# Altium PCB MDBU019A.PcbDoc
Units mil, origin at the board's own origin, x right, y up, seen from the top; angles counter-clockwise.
Board outline 2500 x 2300 mil, 2 copper layers (Top Layer, Bottom Layer), stack 62 mil thick; 49 components, 19 nets, 113 pads, 75 vias.
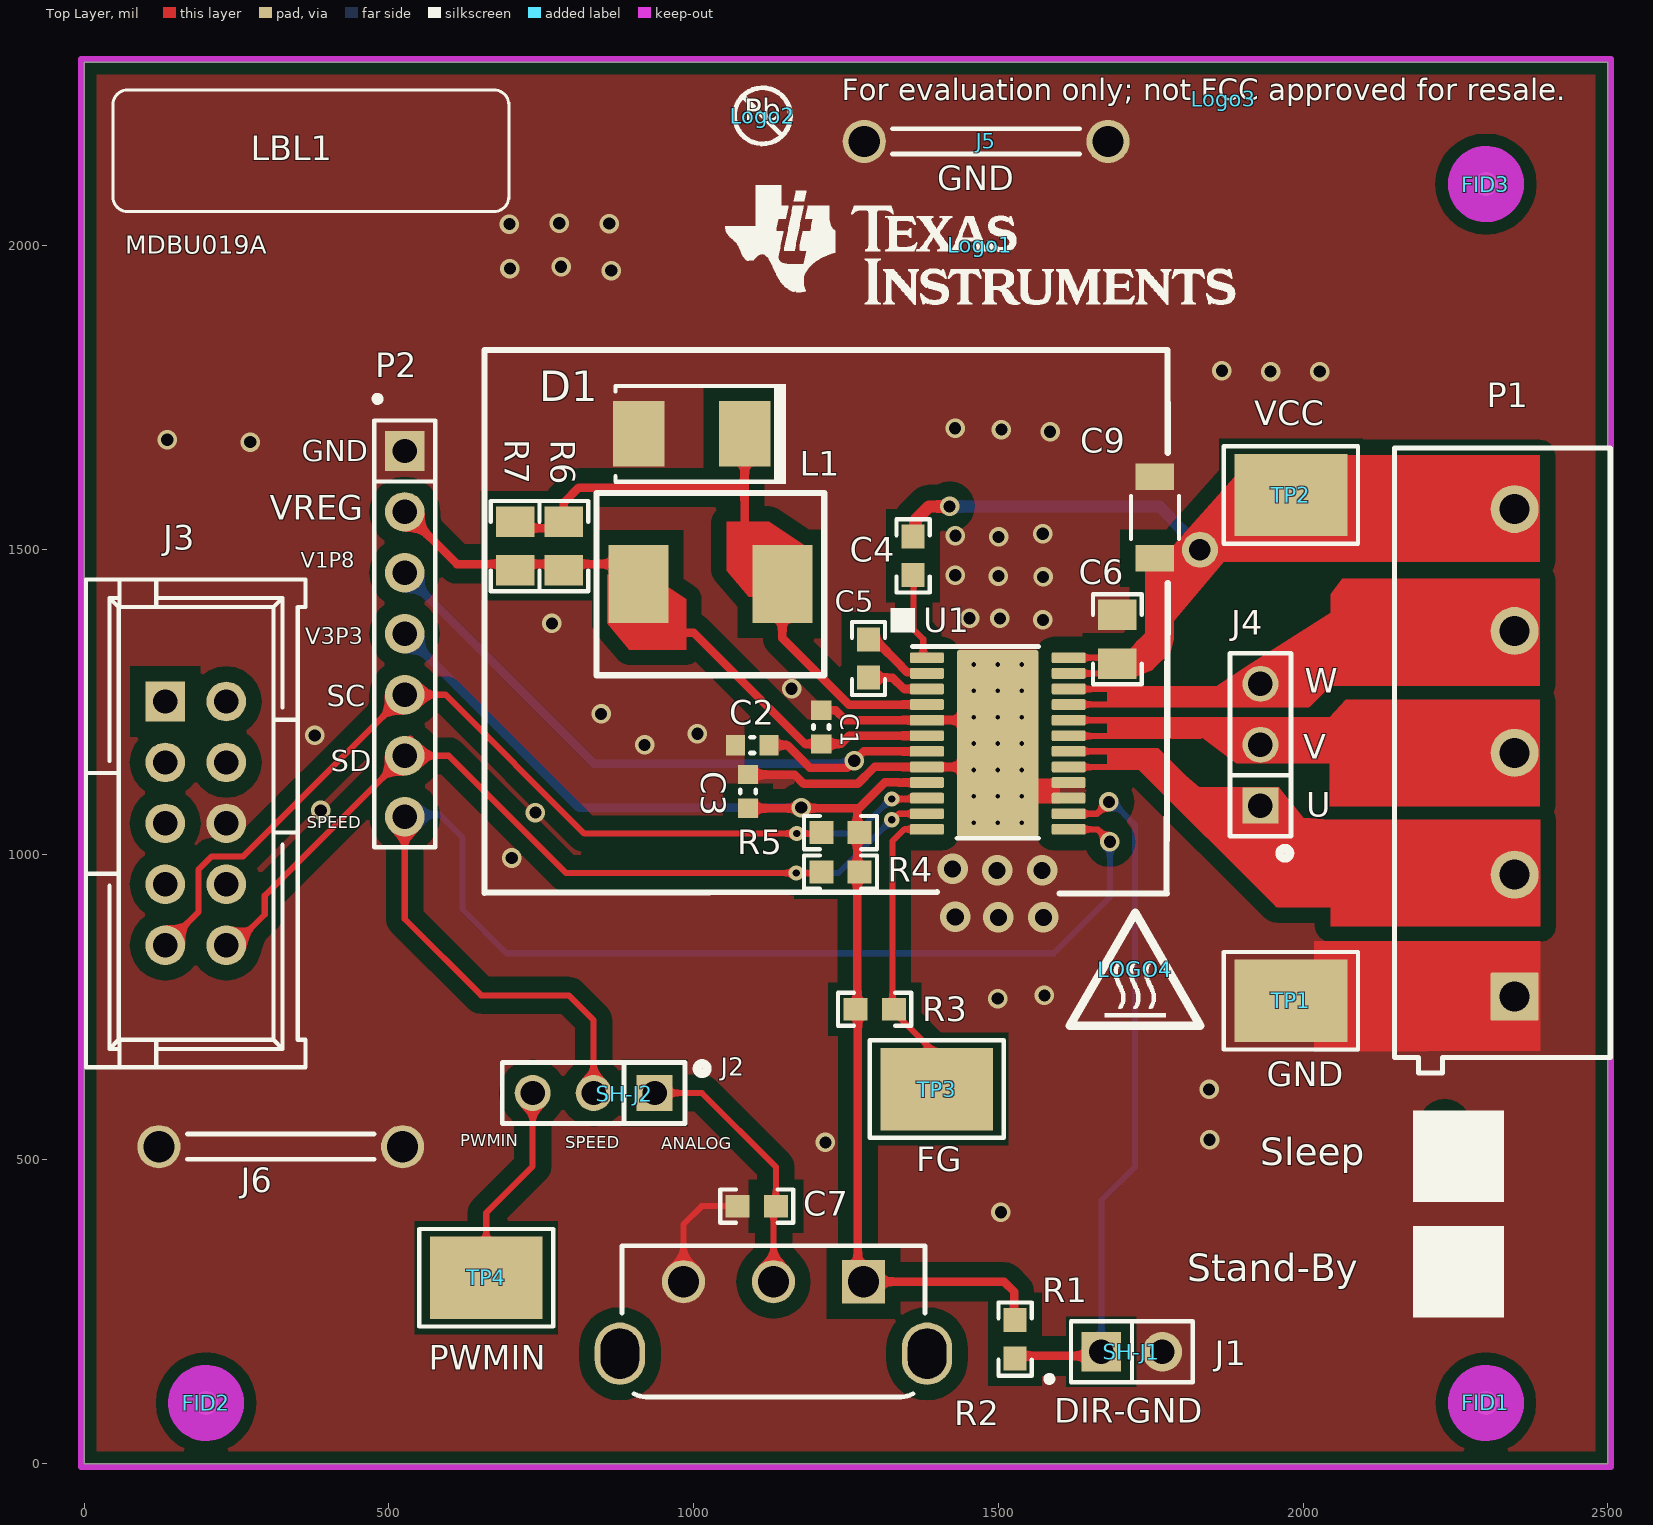
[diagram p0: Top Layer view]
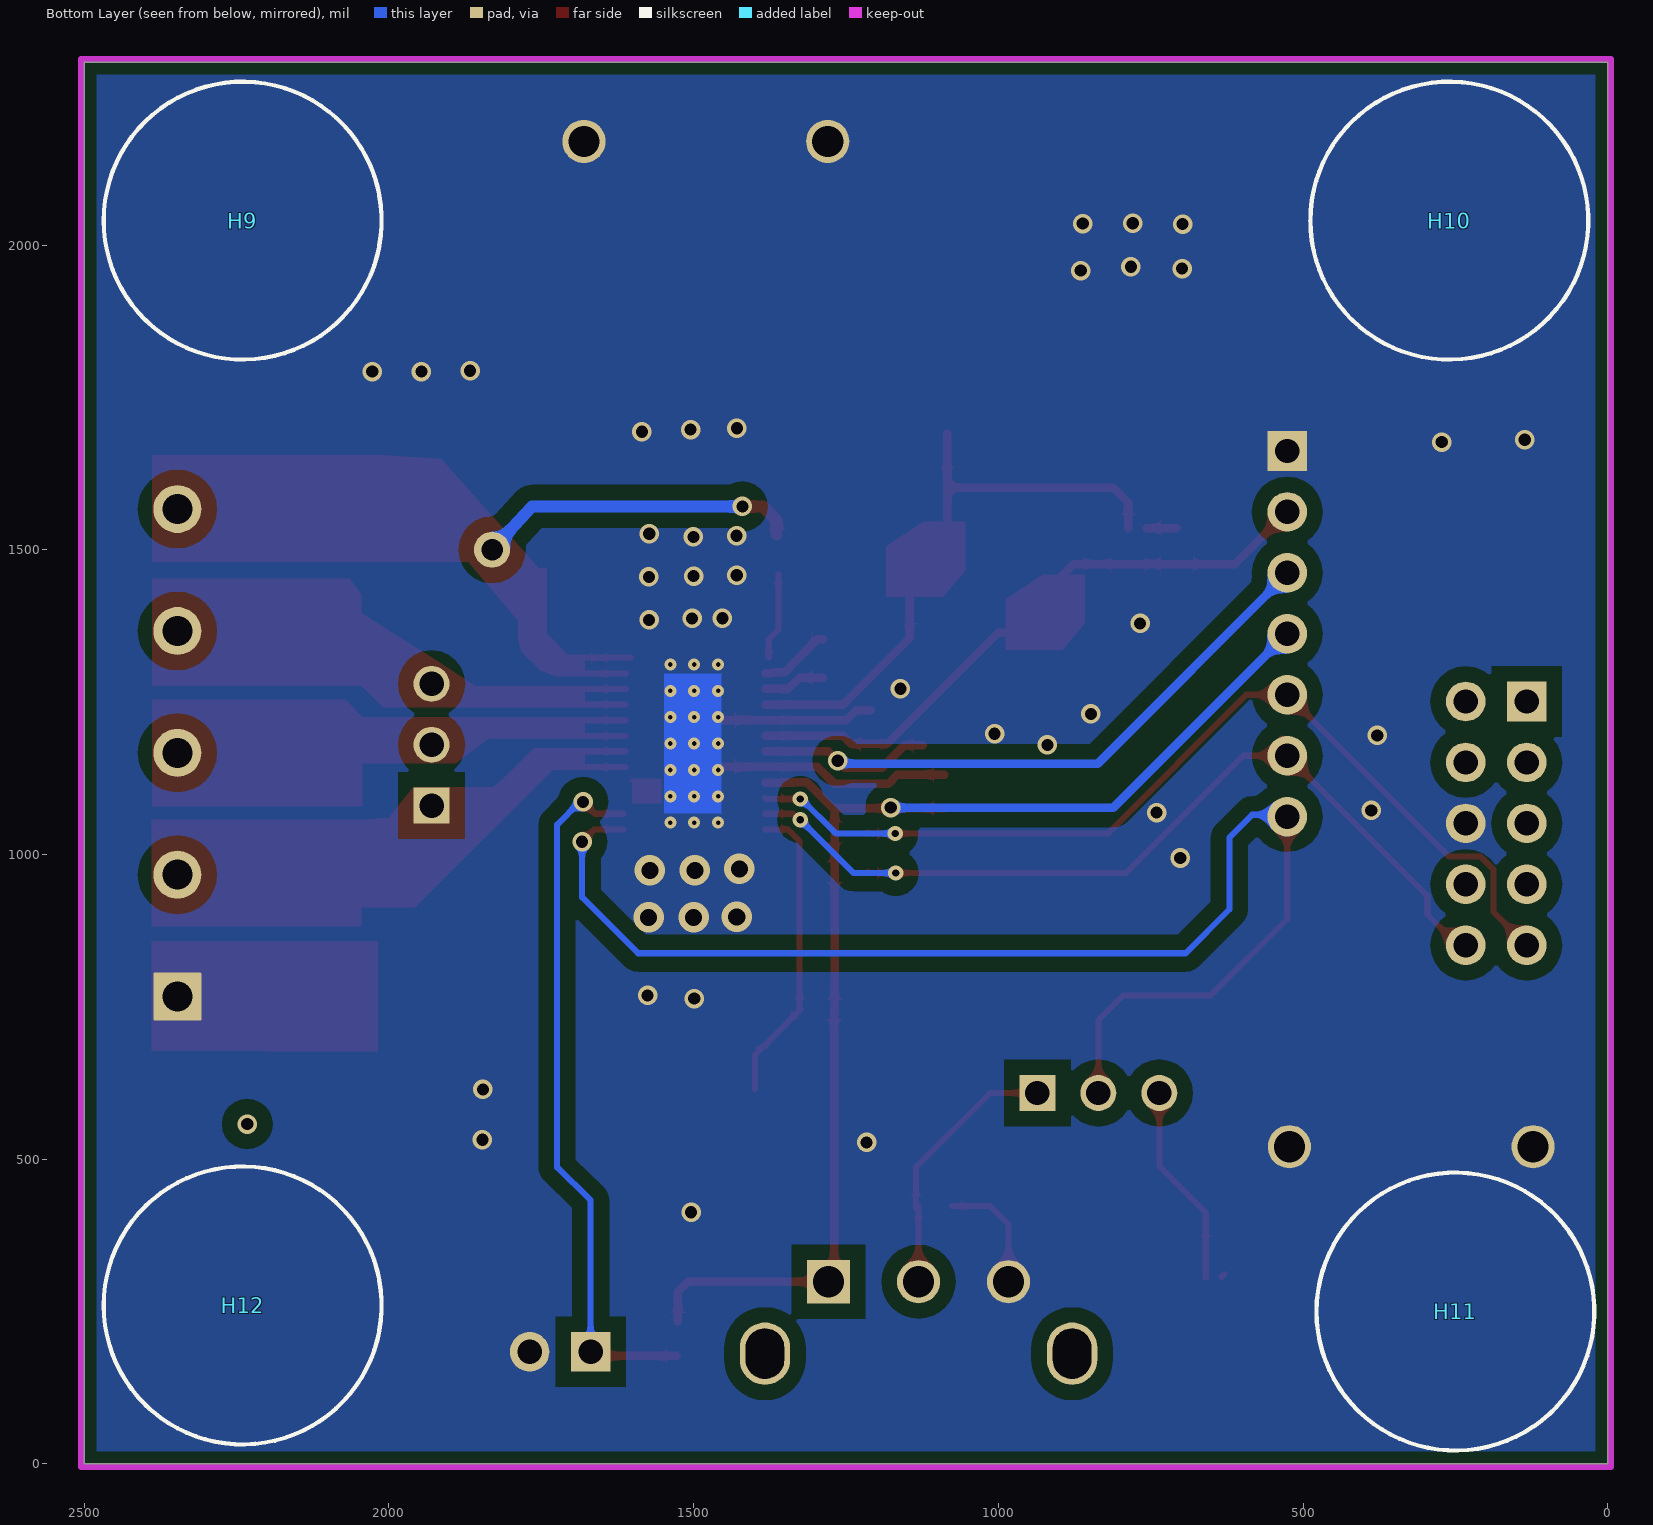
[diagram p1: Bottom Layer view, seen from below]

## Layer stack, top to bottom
Top Solder: solder mask 0.4, Solder Resist, Dk 3.5
Top Layer: signal copper 1.4
Dielectric1: core 59.2, FR-4, Dk 4.8
Bottom Layer: signal copper 1.4
Bottom Solder: solder mask 0.4, Solder Resist, Dk 3.5

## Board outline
0,0 0,2300 2500,2300 2500,0

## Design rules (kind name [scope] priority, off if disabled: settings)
AcuteAngle [All] p1: minimum=4.50000000000000E+0001 checktracksonly=FALSE
AssemblyTestPointUsage [All] p1: valid=2
Clearance Clearance_Keepouts [((IsTrack Or IsArc) And Not InPoly) And IsFree and IsKeepOut vs ((IsTrack Or IsArc) And Not InPoly) And IsFree and IsKeepOut] p1: gap=0
Clearance Clearance_BoardEdge_MountingHoles [OnCopper and InComponentClass('Mounting Holes') vs IsKeepOut] p2: gap=40
Clearance Clearance_BoardEdge_Poly [OnCopper and InPoly vs IsKeepOut] p3: gap=20
Clearance Clearance_BoardEdge [OnCopper and Not InComponentClass('Logo') and not InComponentClass('FiducialMark') and not InRegion(1000,500,4000,800) and Not IsKeepout vs IsKeepOut] p4: gap=75
Clearance Clearance_Poly [InPolygon] p5: gap=25
Clearance [All] p6: gap=7.84
ComponentClearance ComponentClearance_NetTies [InComponentClass('NetTies')] p1: gap=0 collisioncheckmode=3 verticalgap=0 showdistances=FALSE
ComponentClearance ComponentClearance_Shunt [InComponentClass('Header') vs InComponentClass('Shunt')] p2: gap=0 collisioncheckmode=3 verticalgap=0 showdistances=FALSE
ComponentClearance ComponentClearance_1 [All] p3: gap=10 collisioncheckmode=3 verticalgap=10 showdistances=FALSE
ComponentClearance ComponentClearance_Logo [InComponentClass('Logo')] p4: gap=50 collisioncheckmode=3 verticalgap=10 showdistances=FALSE
ComponentClearance ComponentClearance_ScrewToNut [(HasFootprint('NY PMS 440 0025 PH')) vs (HasFootprint('Keystone_1902C'))] p5: gap=5 collisioncheckmode=3 verticalgap=10 showdistances=FALSE
ComponentClearance ComponentClearance_MountingHoles [InComponentClass('Mounting Holes')] p6: gap=250 collisioncheckmode=3 verticalgap=100000 showdistances=FALSE
ComponentClearance ComponentClearance_SmallPassives [HasFootprint('0201*') or HasFootprint('0402*') or HasFootprint('0508') or HasFootprint('0603*') or HasFootprint('0612') or HasFootprint('0805*') or HasFootprint('0815*') or HasFootprint('0830*') or HasFootprint('1206*') or HasFootprint('1210*') or HasFootprint('1808*') or HasFootprint('1812*') or HasFootprint('1825*') or HasFootprint('2010*') or HasFootprint('2220*') or HasFootprint('2225*') or HasFootprint('2512*') or HasFootprint('2728*') or HasFootprint('3518*') vs HasFootprint('0201*') or HasFootprint('0402*') or HasFootprint('0508') or HasFootprint('0603*') or HasFootprint('0612') or HasFootprint('0805*') or HasFootprint('0815*') or HasFootprint('0830*') or HasFootprint('1206*') or HasFootprint('1210*') or HasFootprint('1808*') or HasFootprint('1812*') or HasFootprint('1825*') or HasFootprint('2010*') or HasFootprint('2220*') or HasFootprint('2225*') or HasFootprint('2512*') or HasFootprint('2728*') or HasFootprint('3518*')] p7: gap=20 collisioncheckmode=3 verticalgap=10 showdistances=FALSE
ComponentClearance ComponentClearance_THtoSMT [IsThruComponent vs IsSMTComponent] p8: gap=100 collisioncheckmode=3 verticalgap=30 showdistances=FALSE
ComponentClearance ComponentClearance_THtoTH [IsThruComponent vs IsThruComponent] p9: gap=118.11 collisioncheckmode=3 verticalgap=30 showdistances=FALSE
DiffPairsRouting [All] p1: maxlimit=100 minlimit=10 mostfreqgap=10 toplayer_minwidth=15 toplayer_maxwidth=15 toplayer_prefwidth=15 bottomlayer_minwidth=15 bottomlayer_maxwidth=15 bottomlayer_prefwidth=15 maxuncoupledlength=1000
FabricationTestPointUsage TestPointUsage [All] p1: valid=2 allowmultiple=FALSE
FabricationTestpoint Testpoint [All] p1: side=3 testpointundercomponent=TRUE minsize=40 maxsize=100 preferedsize=60 minholesize=0 maxholesize=40 preferedholesize=32 testpointgrid=1 allowsidetop=TRUE allowsidebottom=TRUE usegrid=TRUE gridtolerance=0.01
FanoutControl Fanout_LCC [IsLCC] p1: bgadir=Out bgaviamode=Centered fanoutstyle=Auto fanoutdirection=Alternating viagrid=1 // Fanout_LCC (Default Rule)
FanoutControl Fanout_BGA [IsBGA] p2: bgadir=Out bgaviamode=Centered fanoutstyle=Auto fanoutdirection=Alternating viagrid=1 // Fanout_BGA (Default Rule)
FanoutControl Fanout_Default [All] p4: bgadir=Out bgaviamode=Centered fanoutstyle=Auto fanoutdirection=Alternating viagrid=1 // Fanout_Default (Default Rule)
FanoutControl Fanout_Small [(CompPinCount < 5)] p5: bgadir=Out bgaviamode=Centered fanoutstyle=Auto fanoutdirection=OutThenIn viagrid=1 // Fanout_Small (Default Rule)
HoleSize [All] p1: absolutevalues=TRUE maxlimit=251 minlimit=7 maxpercent=80.000 minpercent=20.000
MinimumAnnularRing MinimumAnnularRing_ThermalPadVias [IsVia and InAnyComponent] p1: minimumring=5.91
MinimumAnnularRing [All] p2: minimumring=6
MinimumSolderMaskSliver MinimumSolderMaskSliver_Logo [InComponentClass('Logo') vs InComponentClass('Logo')] p1: minsoldermaskwidth=0.7
MinimumSolderMaskSliver [All] p2: minsoldermaskwidth=3.94
PlaneConnect [All] p1: planeconnectstyle=Relief reliefexpansion=10 reliefentries=4 reliefconductorwidth=10 reliefairgap=10
PolygonConnect PolygonConnect_5 [All vs IsNamedPolygon('Bottom Layer-GND')] p1: connectstyle=Direct reliefconductorwidth=10 reliefentries=4 polygonreliefangle="90 Angle" airgapwidth=10
PolygonConnect PolygonConnect_4 [All vs IsNamedPolygon('Top Layer-GND')] p2: connectstyle=Direct reliefconductorwidth=10 reliefentries=4 polygonreliefangle="90 Angle" airgapwidth=10
PolygonConnect PolygonConnect_3 [All vs IsNamedPolygon('Top Layer-GND')] p3: connectstyle=Direct reliefconductorwidth=10 reliefentries=4 polygonreliefangle="90 Angle" airgapwidth=10
PolygonConnect PolygonConnect_2 [All vs IsNamedPolygon('Bottom Layer-GND2')] p4: connectstyle=Direct reliefconductorwidth=10 reliefentries=4 polygonreliefangle="90 Angle" airgapwidth=10
PolygonConnect PolygonConnect_1 [All vs IsNamedPolygon('Top Layer-GND2')] p5: connectstyle=Direct reliefconductorwidth=10 reliefentries=4 polygonreliefangle="90 Angle" airgapwidth=10
PolygonConnect [All] p6: connectstyle=Relief reliefconductorwidth=10 reliefentries=4 polygonreliefangle="90 Angle" airgapwidth=10
RoutingVias [All] p1: holewidth=16 width=34 viastyle="Through Hole" minholewidth=7.87 minwidth=19 maxholewidth=40 maxwidth=65
RoutingVias ThermalPadVias [IsVia and InAnyComponent] p2: holewidth=7.87 width=19.68 viastyle="Through Hole" minholewidth=7.87 minwidth=19.68 maxholewidth=12.99 maxwidth=23.62
SMDToCorner [All] p1: distance=30000
SilkToSilkClearance SilkToSilkClearance_pblogo [(HasFootprint('Pb-Free_Overlay_Medium') OR HasFootprint('Pb-Free_Overlay_Small')) vs (HasFootprint('Pb-Free_Overlay_Medium') OR HasFootprint('Pb-Free_Overlay_Small'))] p1: silktosilkclearance=0
SilkToSilkClearance [All] p2: silktosilkclearance=5
SilkToSolderMaskClearance SilkscreenOverComponentPads [IsPad] p1: minsilkscreentomaskgap=5 clearancetoexposedcopper=TRUE
SolderMaskExpansion [All] p1: expansion=1.97
Width [All] p1: maxlimit=100 minlimit=6 preferedwidth=10 checkconnectedcopper=TRUE
16 further rules are at their usual default settings.

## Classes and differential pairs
component class AssemblyNote: ZZ1 ZZ2 ZZ3 ZZ4 ZZ5
component class FiducialMark: FID1 FID2 FID3
component class MDBU019A_EVM_Hardware: FID1 FID2 FID3 H9 H10 H11 H12 LBL1 Logo1 Logo2 Logo3 LOGO4 SH-J1 SH-J2 ZZ1 ZZ2 ZZ3 ZZ4 ZZ5
component class Logo: Logo1
component class MDBU019A: C1 C2 C3 C4 C5 C6 C7 C9 D1 J1 J2 J3 J4 J5 J6 L1 P1 P2 R1 R2 R3 R4 R5 R6 R7 TP1 TP2 TP3 TP4 U1
component class Shunt: SH-J1 SH-J2
component class Header: J1 J2 J4 P2
component class Label: LBL1

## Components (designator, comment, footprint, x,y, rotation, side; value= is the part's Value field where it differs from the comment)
C1 "C1608X5R1A106M080AC" 0603L 1209.51,1209.03 r90 top
C2 "C1608X5R1E105K080AC" 0603L 1096.24,1179.45 r0 top
C3 "C1608X5R1E105K080AC" 0603L 1089.2,1103.43 r270 top
C4 "06035C104KAT2A" 0603 1360,1490 r270 top
C5 "06031C103KAT2A" 0603 1286.98,1321.53 r90 top
C6 "C2012X5R1H475K125AB" 0805_HV 1695.32,1353.14 r270 top
C7 "06035C104KAT2A" 0603 1103.64,422.9 r180 top
C9 "C3216X5R1H106K160AB" 1206_180 1756.76,1553 r90 top
D1 "VS-10BQ030HM3/5BT" SMB 996.79,1690.24 r180 top
FID1 "Fiducial" Fiducial10-30 2300,100 r90 top
FID2 "Fiducial" Fiducial10-30 200,100 r90 top
FID3 "Fiducial" Fiducial10-30 2300,2100 r90 top
H9 "SJ-5303 (CLEAR)" Bumpon_SJ5003Transparent 2240,2040 r180 bottom
H10 "SJ-5303 (CLEAR)" Bumpon_SJ5003Transparent 260,2040 r180 bottom
H11 "SJ-5303 (CLEAR)" Bumpon_SJ5003Transparent 250,250 r180 bottom
H12 "SJ-5303 (CLEAR)" Bumpon_SJ5003Transparent 2240,260 r180 bottom
J1 "90120-0122" CONN_90120-0122 1719.13,183.93 r0 top
J2 "PEC03SAAN" CONN_PEC03SAAN 835.93,608.59 r180 top
J3 "5103308-1" CONN_5103308-1 183.08,1051 r270 top
J4 "PEC03SAAN" CONN_PEC03SAAN 1930,1180 r90 top
J5 "D3082-05" Harwin_D3082-05 1480,2170 r180 top
J6 "D3082-05" Harwin_D3082-05 322.53,520.54 r180 top
L1 "DR74-470-R" DR74 1027.3,1443.61 r0 top
LBL1 "Size: 0.65\" x 0.20 \"" Label_650x200 371.95,2154.71 r0 top
Logo1 "Texas Instruments" TI_Stacked_Overlay_Small 1470,2000 r0 top
Logo2 "Pb-Free Symbol" Pb-Free_Overlay_Small 1113,2212 r0 top
Logo3 "FCC disclaimer" FCC_disclaimer 1870,2240 r0 top
LOGO4 "CAUTION HOT SURFACE" IEC_HotSurface_Small 1724.48,811.69 r0 top
P1 "ED120/5DS" On-Shore_ED120_5DS 2347.03,1166.77 r90 top
P2 "TSW-107-07-G-S" TSW-107-07-G-S 525.93,1362.05 r270 top
R1 "CRCW060310K0JNEA" 0603 1527.41,204.86 r270 top
R2 "296XD253B1N" CTS_296X 1131,299 r180 top
R3 "CRCW06034K75FKEA" 0603 1297,746 r0 top
R4 "CRCW06034K75FKEA" 0603 1241,971 r180 top
R5 "CRCW06034K75FKEA" 0603 1241,1036 r180 top
R6 "CRCW080578R7FKEA" 0805_HV 787.14,1506.04 r90 top
R7 "CRCW080578R7FKEA" 0805_HV 707.14,1506.04 r90 top
SH-J1 "969102-0000-DA" SNT-100-BK-G 1719.13,183.93 r0 top
SH-J2 "969102-0000-DA" SNT-100-BK-G 886.91,607.14 r0 top
TP1 "5016" Testpoint_Keystone_Compact 1980,760 r180 top
TP2 "5016" Testpoint_Keystone_Compact 1980,1590 r180 top
TP3 "5016" Testpoint_Keystone_Compact 1399,615 r180 top
TP4 "5016" Testpoint_Keystone_Compact 659.68,305.63 r180 top
U1 "DRV10983SQPWPRQ1" PWP0024B_N 1499,1182 r0 top
ZZ1 "This Assembly Note is for PCB labels only" AssemblyNoteLabel 188.21,3922.4 r0 top
ZZ2 "This Assembly Note will show in the PcbDoc and associated outputs" AssemblyNote 185,3829.11 r0 top
ZZ3 "This Assembly Note will show in the PcbDoc and associated outputs" AssemblyNote 185,3740.56 r0 top
ZZ4 "This Assembly Note will show in the PcbDoc and associated outputs" AssemblyNote 185,3652 r0 top
ZZ5 "With a marker put an \"x\" in the box Stand-By on the PCB" AssemblyNote 186.19,3563.52 r0 top

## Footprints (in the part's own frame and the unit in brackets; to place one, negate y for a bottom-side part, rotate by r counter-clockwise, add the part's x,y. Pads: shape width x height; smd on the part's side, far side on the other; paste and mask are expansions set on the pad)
0603 [mm] "0603 from SM-752 data"
  rect 1x0.95 smd: 1(-0.8,0) 2(0.8,0)
  silkscreen extent -1.52,-0.69 1.52,0.69, body extent -0.87,-0.47 0.87,0.47, height 1
0603L [mm] "0603 from SM-752 data"
  rect 0.8x0.85 smd: 1(-0.7,0) 2(0.7,0)
  silkscreen extent -0.07,-0.33 0.07,0.33, body extent -0.87,-0.47 0.87,0.47, height 1
0805_HV [mil] "0805 with 30mil clearance between pads"
  rect 50x63 smd: 1(-40,0) 2(40,0)
  silkscreen extent -74,-40 74,40, body extent -43,-29 43,29, height 57
1206_180 [mm] "1206_180"
  rect 1.1x1.6 smd: 1(-1.7,0) 2(1.7,0)
  silkscreen extent -0.9,-1 0.9,1, body extent -1.75,-0.95 1.75,0.95, height 1.8
AssemblyNote [mil] "Assembly Note"
AssemblyNoteLabel [mil] "Assembly Note for PCB Labels"
Bumpon_SJ5003Transparent [mil] "3M Hemispherical Bumpon transparent"
  round 1 on Mech4: 0(0,0)
  silkscreen extent -228,-228 228,228, body extent -219,-218 219,218, height 197
CONN_90120-0122 [mm] "Molex"
  rect 1.65x1.65 hole 1.016 mask+0: 1(-1.27,0)
  round 1.65 hole 1.016 mask+0: 2(1.27,0)
  silkscreen extent -3.56,-1.27 2.54,1.27, body extent -2.54,-1.27 2.54,1.27, height 9.29
CONN_5103308-1 [mm] "TE Connectivity (AMP) Rev E datasheet"
  rect 1.65x1.65 hole 1.016 mask+0: 1(-5.08,-1.27)
  round 1.65 hole 1.016 mask+0: 2(-5.08,1.27) 3(-2.54,-1.27) 4(-2.54,1.27) 5(0,-1.27) 6(0,1.27) 7(2.54,-1.27) 8(2.54,1.27) 9(5.08,-1.27) 10(5.08,1.27)
  silkscreen extent -10.16,-4.57 10.16,4.57, body extent -10.16,-4.57 10.16,4.57, height 9.87
CONN_PEC03SAAN [mm] "SULLINS"
  rect 1.5x1.5 hole 1.016: 1(-2.54,0)
  round 1.5 hole 1.016: 2(0,0) 3(2.54,0)
  silkscreen extent -4.72,-1.27 3.81,1.27, body extent -3.84,-1.3 3.84,1.3, height 8.38
CTS_296X [mm] "TH, 3-Leads, Body 6.3x12.5mm, Pitch 3.75mm"
  rect 1.8x1.8 hole 1.3: 1(-3.75,0)
  round 1.8 hole 1.3: 2(0,0) 3(3.75,0)
  oval 2.1x2.6 hole 1.6 slot 2.1 at 90 deg: MH1(-6.4,3) MH2(6.4,3)
  silkscreen extent -6.32,-1.5 6.32,4.8, body extent -7.1,-1.5 7.1,18.5, height 16.53
DR74 [mm]
  rect 2.5x3.25 smd: 1(-3,0) 2(3,0)
  silkscreen extent -4.75,-3.8 4.75,3.8, body extent -3.8,-3.8 3.8,3.8, height 4.35
FCC_disclaimer [mil]
Fiducial10-30 [mm]
  round 1 smd mask+1: 1(0,0)
  Top Layer keep-out circle w1.678: c0,0 r0.75
Harwin_D3082-05 [mm] "Shorting Plug, 10.16mm spacing, TH"
  round 1.8 hole 1.3: 1(-5.08,0) 2(5.08,0)
  silkscreen extent -3.9,-0.53 3.9,0.53, body extent -5.6,-0.52 5.61,0.52, height 6.63
IEC_HotSurface_Small [mil]
  silkscreen extent -107,-93 107,92
Label_650x200 [mil] "Thermal Transfer Label"
  round 1 on Mech13: 0(0,0)
  silkscreen extent -325,-100 325,100, body extent -325,-100 325,100, height 1
On-Shore_ED120_5DS [mm] "TH, 5-Leads, Body 25.4x9mm, Pitch 5.08mm"
  rrect5% 2x2 hole 1.25: 1(-10.16,0)
  round 2 hole 1.25: 2(-5.08,0) 3(0,0) 4(5.08,0) 5(10.16,0)
  silkscreen extent -13.34,-4 12.7,5, body extent -13.4,-4 12.7,5, height 13
Pb-Free_Overlay_Small [mil]
  silkscreen extent -46,-46 46,46
PWP0024B_N [mm] "TSOP, 24-Leads, Body 7.9x4.5mm (max), Pitch 0.65mm, IPC Medium Density"
  rrect22% 1.4x0.45 smd: 1(-2.95,3.575) 2(-2.95,2.925) 3(-2.95,2.275) 4(-2.95,1.625) 5(-2.95,0.975) 6(-2.95,0.325) 7(-2.95,-0.325) 8(-2.95,-0.975) 9(-2.95,-1.625) 10(-2.95,-2.275) 11(-2.95,-2.925) 12(-2.95,-3.575) 13(2.95,-3.575) 14(2.95,-2.925) 15(2.95,-2.275) 16(2.95,-1.625) 17(2.95,-0.975) 18(2.95,-0.325) 19(2.95,0.325) 20(2.95,0.975) 21(2.95,1.625) 22(2.95,2.275) 23(2.95,2.925) 24(2.95,3.575)
  rrect6% 3.4x7.8 smd paste-2 mask-2: 25(0,0)
  rrect4% 2.4x5.16 on Top Paste: 25(0,0)
  rrect4% 2.4x5.16 on Top Solder: 25(0,0)
  silkscreen extent -3.55,-3.95 1.7,4.05, body extent -3.21,-3.9 3.21,3.9, height 1.2
SMB [mil] "Molded Diode, 2-Leads, Body 5.4x3.6mm, IPC Medium Density, based on OnSemi component dimensions"
  rect 85x107.99 smd: 1(-87.01,0) 2(87.01,0)
  silkscreen extent -155,-82 125,82, body extent -106,-71 106,71, height 91
SNT-100-BK-G [mil] "Samtec STEP model"
  round 1 on Mech3: 0(0,0)
  body extent -100,-50 100,50, height 344
Testpoint_Keystone_Compact [mil] "Compact SMT test point"
  rect 185x135 smd: 1(0,0)
  silkscreen extent -110,-80 110,80, body extent -75,-56 75,56, height 91
TI_Stacked_Overlay_Small [mil]
  silkscreen extent -418,-98 418,98
TSW-107-07-G-S [mm] "Samtec 100mil, 1x7, 230 mil above insulator"
  rect 1.65x1.65 hole 1.016 mask+0: 1(-7.62,0)
  round 1.65 hole 1.016 mask+0: 2(-5.08,0) 3(-2.54,0) 4(0,0) 5(2.54,0) 6(5.08,0) 7(7.62,0)
  silkscreen extent -9.91,-1.27 8.89,1.27, body extent -8.89,-1.27 8.89,1.27, height 8.38

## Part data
C1: "CAP, CERM, 10 µF, 10 V, +/- 20%, X5R, 0603"
C2 C3: "CAP, CERM, 1 µF, 25 V, +/- 10%, X5R, 0603"
C4 C7: "CAP, CERM, 0.1 µF, 50 V, +/- 10%, X7R, 0603"
C5: "CAP, CERM, 0.01 µF, 100 V, +/- 10%, X7R, 0603"
C6: "CAP, CERM, 4.7 µF, 50 V, +/- 10%, X5R, 0805"
C9: "CAP, CERM, 10 µF, 50 V, +/- 10%, X5R, 1206"
D1: "Diode, Schottky, 30 V, 1 A, AEC-Q101, SMB"
FID1 FID2 FID3: "Fiducial mark.  There is nothing to buy or mount."
H9 H10 H11 H12: "Bumpon, Hemisphere, 0.44 X 0.20, Clear"
J1: "Header, 100mil, 2x1, Tin, TH"
J2 J4: "Header, 100mil, 3x1, Tin, TH"
J3: "Header (shrouded), 100mil, 5x2, Gold, TH"
J5 J6: "1mm Uninsulated Shorting Plug, 10.16mm spacing, TH"
L1: "Inductor, Shielded Drum Core, Ferrite, 47 µH, 1.15 A, 0.216 ohm, SMD"
LBL1: library part THT-14-423-10, "Thermal Transfer Printable Labels, 0.650\" W x 0.200\" H - 10,000 per roll"
Logo1: library part TI_Logo, "Texas Instrument Corporate Signature"
Logo2: library part Pb-Free
Logo3: library part FCC_disclaimer, "FCC_disclaimer"
LOGO4: library part IEC_HotSurface, "IEC 61010-1 Hot Surface Warning"
P1: "Terminal Block, 5.08 mm, 5x1, Brass, TH"
P2: "Header, 100mil, 7x1, Gold, TH"
R1: "RES, 10 k, 5%, 0.1 W, 0603"
R2: "Trimmer, 25k ohm, 0.15W, TH"
R3 R4 R5: "RES, 4.75 k, 1%, 0.1 W, 0603"
R6 R7: "RES, 78.7, 1%, 0.125 W, 0805"
SH-J1 SH-J2: "Shunt, 100mil, Gold plated, Black"
TP1 TP2 TP3 TP4: "Test Point, Compact, SMT"
U1: "Industrial, Three-Phase, Sensorless BLDC Motor Driver, PWP0024B (TSSOP-24)"
ZZ1: library part AssemblyNoteLabel
ZZ2 ZZ3 ZZ4: library part AssemblyNote
ZZ5: library part AssemblyNote, "This Assembly Note will show in the PcbDoc and associated outputs"

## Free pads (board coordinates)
  round 59.06 hole 35.43: 0(1830.74,1500)

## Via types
v1: diameter 32, hole 20, Top Layer to Bottom Layer, 44 vias
v2: diameter 19.68, hole 7.87, Top Layer to Bottom Layer, 15 vias
v3: diameter 19.68, hole 7.87, Top Layer to Bottom Layer, tented both sides, 6 vias
v4: diameter 50, hole 28, Top Layer to Bottom Layer, 6 vias
v5: diameter 25, hole 12, Top Layer to Bottom Layer, 4 vias

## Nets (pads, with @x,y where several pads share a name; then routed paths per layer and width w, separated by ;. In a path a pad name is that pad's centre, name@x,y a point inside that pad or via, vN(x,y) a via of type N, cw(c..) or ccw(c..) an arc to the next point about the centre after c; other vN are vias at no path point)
CPN: C5.1 U1.3 | length 103.5
  Top Layer w14: C5.1 1326.47,1290.03 1344.94,1271.57 U1.3
CPP: C5.2 U1.2 | length 119.4
  Top Layer w14: C5.2 1297.03,1353.02 1340.46,1309.6 1340.46,1308.88 1350.29,1299.05 1369.11,1299.05 1371,1297.16 U1.2
DIR: J1.1 R1.2 U1.14 | length 1173.8
  Top Layer w10: U1.14 1662.04,1066.84 v1(1681.36,1086.17) ; J1.1@1662.5,177.3 J1.1
  Top Layer w14: R1.2@1527.41,177.3 J1.1@1662.5,177.3
  Bottom Layer w10: J1.1 1669.13,432.63 1670.65,434.15 1724.1,486.68 1724.1,1049.08 1687.02,1086.17 v1(1681.36,1086.17) 1681.36,1078.95 v1@1680.23,1077.81
FG: R3.2 TP3.1 U1.12 | length 503.2
  Top Layer w10: U1.12 1345.28,1041.25 1326.03,1022 1326.03,747.47 1324.56,746 1399,671.56 TP3.1
GND: C1.2 C2.1 C3.1 C6.1 C7.2 C9.2 D1.2 J1.2 J3.6 J5.1 J5.2 J6.1 J6.2 P1.1 P2.1 R2.3 TP1.1 U1.5 U1.8 U1.15 U1.16 U1.25@1499,1182 | length 980.1
  Top Layer w10: R2.3 983.36,392.96 1013.3,422.9 C7.2@1076.08,422.9 ; U1.25@1510,1100 U1.25@1517.7,1092.3 ; U1.25@1510,1110 U1.25@1517.3,1117.3
  Top Layer w14: C3.1 1165.53,1130.99 1180.49,1116.03 1269.36,1116.03 1295.06,1141.72 ; C1.2 1232.99,1236.59 1249.19,1220.39 U1.5 1460.61,1220.39 v2(1499,1182) 1460.61,1143.61 U1.8 1296.95,1143.61
  Bottom Layer w20: 1481,1095 1486,1090
  other v1: 1504.07,413.03 1216.28,527.43 1846.5,531.89 1845.64,614.54 1499.09,763.65 1575.68,768.64 701.43,994.21 740.3,1068.69 388.16,1072.18 919.43,1179.83 378.28,1195.22 1006.12,1198.24 848.06,1230.54 1160.66,1272.04 767.5,1379.19 1573.05,1384.73 1502.55,1387.35 1452.74,1387.6 1573.3,1455.52 1499.97,1456.81 1429.22,1458.1 1500.23,1520.99 1429.6,1522.97 1572.72,1526.09 272.52,1676.56 136.41,1680.59 1584.85,1693.59 1504.9,1697.24 1429.07,1699.42 1946.61,1792.44 2027.41,1792.44 1866.86,1793.76 864.78,1957.97 698.64,1961.44 782.45,1964.42 697.65,2034.35 861.51,2035.16 779.48,2035.84
  other v2: 1459.63,1095.39 1499,1095.39 1538.37,1095.39 1459.63,1138.69 1499,1138.69 1538.37,1138.69 1459.63,1182 1538.37,1182 1459.63,1225.31 1499,1225.31 1538.37,1225.31 1459.63,1268.61 1499,1268.61 1538.37,1268.61
  other v3: 1459.63,1052.08 1499,1052.08 1538.37,1052.08 1459.63,1311.92 1499,1311.92 1538.37,1311.92
  other v4: 1500.01,896.65 1574.03,896.65 1429.3,897.76 1497.8,973.99 1571.82,973.99 1424.88,976.2
NetC7_1: C7.1 J2.1 R2.2 | length 483.1
  Top Layer w10: J2.1 1013.57,608.59 1134.84,487.32 C7.1@1134.84,419.25 ; R2.2@1118.39,286.39 1113.16,286.39 1113.16,306.39 1123.61,316.84 R2.2@1125.52,316.84 ; R2.2 1131.2,299.2 C7.1@1131.2,422.9
PWMIN: J2.3 TP4.1 | length 340.5
  Top Layer w10: TP4.1@629.24,311.31 TP4.1@633.47,307.09 ; TP4.1 659.68,411.96 735.93,488.2 J2.3
SCL: J3.9 P2.5 R5.2 U1.10 | length 1621.2
  Top Layer w10: J3.9 187.76,905.68 187.76,975.54 209.03,996.82 260.7,996.82 P2.5 593.12,1262.05 820.87,1034.3 v5(1169.36,1034.3) 1211.74,1034.3 R5.2@1213.44,1036 ; v5(1325,1091) 1381.43,1091 U1.10
  Bottom Layer w10: v5(1169.36,1034.3) 1266.46,1034.3 ; 1268.59,1036.43 1323.16,1091 v5(1325,1091)
SDA: J3.10 P2.6 R4.2 U1.11 | length 1463.5
  Top Layer w10: J3.10 245.75,851 296.24,901.48 296.24,932.36 P2.6 598.2,1162.05 790.73,969.52 v5(1168.49,969.52) 1211.96,969.52 R4.2@1213.44,971 ; P2.6@535,1188.82 P2.6@535,1190 ; v5(1325,1057) 1326.84,1057 1336.68,1066.84 U1.11
  Bottom Layer w10: v5(1168.49,969.52) 1237.52,969.52 v5(1325,1057)
SPEED: J2.2 P2.7 U1.13 | length 2285.8
  Top Layer w10: P2.7 525.93,894.1 651.22,768.81 795.14,768.81 835.93,728.03 J2.2 ; U1.13 1658.11,1041.25 1658.59,1040.77 1663.23,1040.77 v1(1683,1021)
  Bottom Layer w10: P2.7 P2.7@525.93,1038.5 ; P2.7@530.03,1034.4 P2.7@525.93,1038.5 ; v1(1683,1021) 1683,929.63 1591.22,837.86 692.77,837.86 620.95,909.69 620.95,1027.71 583.51,1065.15 499.28,1065.15 P2.7@525.93,1038.5
SW: D1.1 L1.2 R6.2 R7.2 U1.4 | length 955.9
  Top Layer w14: R7.2@707.14,1535.56 R6.2@756.58,1535.56 ; R6.2@787.14,1535.56 787.14,1577.72 811.18,1601.76 1083.8,1601.76 ; 1083.8,1488.63 1083.8,1601.76 ; D1.1 1083.8,1601.76 ; L1.2@1145.55,1428.46 1145.41,1355.05 1254.49,1245.98 U1.4
U: J4.1 P1.2 U1.17 U1.18 | length 1202.6
  Top Layer w10: U1.17@1611.7,1143.3 1732.7,1143.3 1958,918 2083,918 ; U1.18@1611.7,1169.3 1760.7,1169.3 1911,1019 2084,1019 ; 2083,916 2084,917 2084,919
  Top Layer w40: 2084,919 2084,967 2084,1019
V: J4.2 P1.3 U1.19 U1.20 | length 781.8
  Top Layer w10: U1.19@1611.7,1194.3 1830.7,1194.3 ; U1.20@1611.7,1220.3 2074.3,1220.3 2075,1221 ; 2084,1124 2086,1122
  Top Layer w40: 2084,1124 2084,1162 2084,1219 ; 2290,1162 2291,1161
V1P8: C2.2 P2.3 U1.7 | length 1155.6
  Top Layer w14: C2.2@1124.3,1179.45 1153.61,1179.45 1190.82,1142.24 1251.96,1142.24 v1(1263.52,1153.8) 1278.92,1169.2 U1.7
  Bottom Layer w14: P2.3 525.93,1460.04 836.98,1148.99 1258.71,1148.99 v1(1263.52,1153.8)
V3P3: C3.2 P2.4 R1.1 R2.1 R3.1 R4.1 R5.1 U1.9 | length 2151.4
  Top Layer w10: R3.1@1268.56,746.88 R3.1@1269.44,746 ; R1.1@1525.73,234.09 R1.1@1527.41,232.42
  Top Layer w14: C3.2@1089.22,1075.85 1271.18,1075.85 1313.68,1118.34 1336.32,1118.34 1336.64,1118.02 U1.9 ; R3.1@1268.56,746.88 1268.56,971 1268.56,1036 1268.56,1073.22 ; R2.1@1269.44,308.2 R3.1@1269.44,746 ; R2.1 1509.45,299 1525.73,282.72 R1.1@1525.73,234.09
  Bottom Layer w14: P2.4 811.37,1076.6 1176.89,1076.6 v1(1176.45,1077.04)
VCC: C4.1 C6.2 C9.1 P1.5 pad.0 TP2.1 U1.23 U1.24 | length 1066.5
  Top Layer w10: U1.24@1603,1322.91 1707.91,1322.91 1748.92,1364.55 ; U1.23@1610.7,1296.9 1610.8,1297 1726,1297 1750.07,1306.78 1778.57,1335.28 1783,1354 1783,1428 ; 2089,1559 2090,1560
  Top Layer w20: C4.1@1364,1525 1364,1549 1386,1571 v1(1420,1571)
  Top Layer w40: 2084,1519 2084,1615
  Bottom Layer w20: v1(1420,1571) 1765,1571 pad.0
VCP: C4.2 U1.1 | length 143.6
  Top Layer w10: C4.2@1361,1460 1361,1369 1376.72,1353.28 U1.1@1376.72,1322.91
VREG: C1.1 L1.1 P2.2 R6.1 R7.1 U1.6 | length 964.6
  Top Layer w14: P2.2 611.47,1476.51 707.14,1476.51 787.14,1476.51 876.29,1476.51 L1.1 ; 931.7,1364.08 999.87,1364.08 1182.48,1181.47 C1.1 1241.85,1181.47 1255.17,1194.8 U1.6
W: J4.3 P1.4 U1.21 U1.22 | length 1139.8
  Top Layer w10: U1.22@1610.7,1271.3 1934.3,1271.3 2084,1421 ; U1.21@1611.7,1246.3 2008.3,1246.3 2084,1322 ; 2083,1418 2084,1417
  Top Layer w40: 2084,1319 2084,1322 2084,1362 2084,1417 ; 2290,1362 2291,1361
pads on no net: FID1.1 FID2.1 FID3.1 H9.0 H10.0 H11.0 H12.0 J3.1 J3.2 J3.3 J3.4 J3.5 J3.7 J3.8 LBL1.0 R2.MH1 R2.MH2 SH-J1.0 SH-J2.0 U1.25@1499,1182
copper on no net:
  other v1: 2232.32,557.66

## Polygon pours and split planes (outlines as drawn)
GND on Bottom Layer "Bottom Layer-GND" (solid, remove dead copper, pour order 6): 0,0 0,2500 2500,2500 2500,0
GND on Top Layer "Top Layer-GND" (solid, remove dead copper, pour order 4): -8.85,-18.07 -8.85,2281.93 2491.15,2281.93 2491.15,-18.07

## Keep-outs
Keep-Out Layer:
  lines w10: -5,-5 2505,-5 2505,2305 -5,2305 -5,-5
  text ".Layer_Name" at 577,-858.49 h60

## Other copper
Top Layer:
  rectangle net GND: 1553,1120 1605.99,1123.28
  rectangle net GND: 1553,1084 1601,1125
  rectangle net GND: 1544,1123 1585,1123.28
  region net SW: 1123.93,1545.7 1183.93,1505.7 1183.93,1422.71 1090.7,1422.71 1053.93,1465.7 1053.93,1545.7
  region net VREG: 927.91,1459.14 987.91,1419.14 987.91,1336.15 894.68,1336.15 857.91,1379.14 857.91,1459.14
  region net GND: 2018,676 2389,678 2389,858 2018,858
  region net VCC: 1870,1480 2090,1480 2084,1655 2004,1655 1913.72,1649.63 1754.05,1470 1741.17,1470 1741.17,1350 1760,1350
  region net U: 1679,1170 1679,1143 1734,1143 1958,919 2084,919 2085,920 2083,922 2084,1000 2045,1057 2000,1060 1960,1110 1830,1110 1763,1167 1763,1169
  region net V: 1679,1221 1679,1194 1831,1194 1890,1150 2084,1150 2084,1220
  region net W: 1679,1247 1679,1271 1720,1271.3 1850,1271.3 1914.92,1313.97 2084,1421 2084,1313 2075,1313 2008,1246
  region net VCC: 1735.59,1297 1783.29,1344.69 1780,1440 1746.97,1440 1746.97,1351 1733,1351 1718,1332 1708,1322 1679,1322 1679,1297
  region net VCC: 2044,1480 2388,1480 2388,1655 2044,1655
  region net W: 2044,1277 2388,1277 2388,1452 2064,1452 2045,1427
  region net V: 2044,1079 2388,1079 2388,1254 2070,1254 2044,1225
  region net U: 2045,882 2389,882 2389,1057 2045,1057
  text ".Layer_Name" at 577,-858.49 h60
Bottom Layer:
  rectangle net GND: 1454,1067 1549,1297
  text ".VersionControl_RevNumber" at 4074,1205 h60
  text "UL94V-0" at 3115,1048 h60
  text "SVN:" at 4170,179.5 h60
  text ".Layer_Name" at 577,-858.49 h60

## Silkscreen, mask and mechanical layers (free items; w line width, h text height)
Top Overlay:
  rectangle: 1323.17,1364.28 1363.17,1404.28
  rectangle: 2180,240 2330,390
  rectangle: 2180,430 2330,580
  lines w10: 1399.17,938.18 656.69,937.26 656.96,1402.64 656.81,1827.69 1777.62,1827.99 1777.98,1659.11 ; 1600.22,936.02 1776.3,936.25 ; 1776.17,936.46 1777.98,1445.26
  text "GND" at 1400,2090 h40
  text "MDBU019A" at 67.16,1985.98 h30
  text "VCC" at 1919.91,1704.5 h40
  text "GND" at 356.89,1645.05 h35
  text "VREG" at 304.51,1549.26 h40
  text "V1P8" at 355.6,1470.19 h25
  text "V3P3" at 362.4,1345.27 h27
  text "W" at 2003,1265 h40
  text "SC" at 398.24,1243.27 h35
  text "V" at 2000,1157 h40
  text "SD" at 404.5,1136.37 h35
  text "U" at 2005,1062 h40
  text "SPEED" at 365.02,1043.05 h20
  text "GND" at 1940,620 h40
  text "PWMIN" at 617.44,521.2 h20
  text "SPEED" at 789.32,518.29 h20
  text "ANALOG" at 946.73,516.47 h20
  text "Sleep" at 1930,490 h45
  text "FG" at 1365.39,479.83 h40
  text "Stand-By" at 1810,300 h45
  text "PWMIN" at 565.01,154.15 h40
  text "DIR-GND" at 1591.87,67.56 h40
  text ".Layer_Name" at 577,-858.49 h60
Bottom Overlay:
  text ".Layer_Name" at 577,-858.49 h60
Top Paste:
  text ".Layer_Name" at 577,-858.49 h60
Bottom Paste:
  text ".Layer_Name" at 577,-858.49 h60
Top Solder:
  text ".Layer_Name" at 577,-858.49 h60
  text ".Layer_Name" at 577,-858.49 h60
Bottom Solder:
  text ".Layer_Name" at 577,-858.49 h60
Drill Guide:
  text ".Layer_Name" at 577,-858.49 h60
M1 Board Outline:
  the board outline again, w10
  text ".Layer_Name" at 577,-858.49 h60
M2 Board Dimensions:
  rectangle: 124.5,-410.5 499.5,-285.5
  rectangle: -0.5,-285.5 124.5,-160.5
  lines w7: -0.5,-285.5 999.5,-285.5 ; 124.5,-410.5 124.5,-160.5 ; 249.5,-410.5 249.5,-160.5 ; 499.5,-410.5 499.5,-160.5 ; 749.5,-410.5 749.5,-160.5 ; -0.5,-410.5 -0.5,-160.5 999.5,-160.5 999.5,-410.5 -0.5,-410.5
  lines w10: -0.5,-475.5 -0.5,-455.5 ; 59.5,-485.5 -0.5,-465.5 ; 59.5,-445.5 -0.5,-465.5 ; 223.58,-465.5 -0.5,-465.5 ; 775.42,-465.5 999.5,-465.5 ; 939.5,-485.5 999.5,-465.5 ; 939.5,-445.5 999.5,-465.5 ; 999.5,-475.5 999.5,-455.5
  text "1000 (mil)" at 233.58,-501.49 h60
  text ".Layer_Name" at 577,-858.49 h60
M3 3D STEP Top:
  text ".Layer_Name" at 577,-858.49 h60
M4 3D STEP Bottom:
  text ".Layer_Name" at 577,-858.49 h60
M5 Assembly Top:
  lines w10: -292,-930.17 6308,-930.17 ; -292,-726.83 6310,-726.83 ; -292,-523.5 -292,-1133.5 3713,-1133.5 6310,-1133.5 6310,-523.5 -291.5,-523.5 -291.5,-1133.5 1284,-1133.5 ; 2173,-1133.5 2173,-523.5 ; 3440,-726.83 3440,-523.5 ; 4280,-726.83 4280,-523.5 ; 4902,-1140 4902,-937.17
  text "COMPONENTS MARKED 'DNP' SHOULD NOT BE POPULATED." at 1153.5,-318.5 h60
  text "ASSEMBLY VARIANT:" at 1153,-434 h60
  text ".VariantName" at 2189,-434 h60
  text "PCB VIEWED FROM TOP SIDE" at -228.5,-655.67 h60
  text "BOARD #:" at 2248,-655.67 h60
  text ".PRJ_Number" at 2793.5,-655.67 h60
  text "REV:" at 3638,-655.67 h60
  text ".PCB_Rev" at 3929.5,-655.67 h60
  text "SVN REV:" at 4476,-655.67 h60
  text ".VersionControl_RevNumber" at 4982,-655.67 h60
  text "IGNORE ->" at -228.5,-858.49 h60
  text "PLOT NAME =" at -228.5,-1064.34 h60
  text ".plot_File_Name" at 577,-1064.34 h60
  text "GENERATED    :" at 2250,-1064.34 h60
  text ".Print_Date" at 3119.5,-1064.34 h60
  text ".Print_Time" at 3848.5,-1064.34 h60
  text "TEXAS INSTRUMENTS" at 5113,-1064.34 h60
M6 Assembly Bottom:
  lines w10: -292.5,-727.33 6309.5,-727.33 ; -290.5,-930.67 6309.5,-930.67 ; 1115.5,-1140.5 1115.5,-937.67 ; 1737.5,-727.33 1737.5,-524 ; 2577.5,-727.33 2577.5,-524 ; 3844.5,-1134 3844.5,-524 ; 4733.5,-1134 6309,-1134 6309,-524 -292.5,-524 -292.5,-1134 2304.5,-1134 6309.5,-1134 6309.5,-524
  text "COMPONENTS MARKED 'DNP' SHOULD NOT BE POPULATED." at 6102,-318 h60
  text ".VariantName" at 5058,-434 h60
  text "ASSEMBLY VARIANT:" at 6097,-434 h60
  text ".VersionControl_RevNumber" at 1035.5,-656.17 h60
  text "SVN REV:" at 1541.5,-656.17 h60
  text ".PCB_Rev" at 2088,-656.17 h60
  text "REV:" at 2379.5,-656.17 h60
  text ".PRJ_Number" at 3224,-656.17 h60
  text "BOARD #:" at 3769.5,-656.17 h60
  text "PCB VIEWED FROM BOTTOM SIDE" at 6246,-656.17 h60
  text "IGNORE ->" at 2547.85,-858.49 h60
  text "TEXAS INSTRUMENTS" at 904.5,-1064.84 h60
  text ".Print_Time" at 2169,-1064.84 h60
  text ".Print_Date" at 2898,-1064.84 h60
  text "GENERATED    :" at 3767.5,-1064.84 h60
  text ".plot_File_Name" at 5440.5,-1064.84 h60
  text "PLOT NAME =" at 6246,-1064.84 h60
M9 Title Sheet:
  drawing of 55 lines, arcs and shapes, not listed
  text "1" at 739.84,8036.5 h70
  text "2" at 3235.5,8036.5 h70
  text "3" at 5724.84,8036.5 h70
  text "4" at 8231.51,8036.5 h70
  text "A" at -416.5,6893.5 h70
  text "A" at 14383.5,6893.5 h70
  text "B" at -416.5,4513.5 h70
  text "B" at 14383.5,4513.5 h70
  text "C" at -416.5,2138.5 h70
  text "C" at 14383.5,2138.5 h70
  text "PROJECT TITLE:" at 11343.5,277.5 h45
  text ".PRJ_Title" at 11393.5,144.17 h70
  text "DESIGNED FOR:" at 11343.5,-23.5 h45
  text ".PRJ_Customer" at 11393.5,-163.5 h70
  text "D" at -416.5,-231.5 h70
  text "D" at 14383.5,-231.5 h70
  text "FILE NAME:" at 11343.5,-323.5 h45
  text ".PCB_File_Name_No_Path" at 11393.5,-443.5 h70
  text "Texas Instruments (TI) and/or its licensors do not warrant the accuracy or completeness of this specification" at 6374,-605.34 h45
  text "ENGINEER:" at 11343.5,-613.5 h45
  text "LAYOUT BY:" at 12848.5,-613.5 h45
  text "or any information contained therein. TI and/or its licensors do not warrant that this design will meet" at 6329.01,-718 h45
  text ".PRJ_Engineer" at 11393.5,-768.49 h70
  text ".PCB_Layout" at 12899,-768.49 h70
  text "the specifications, will be suitable for your application or fit for any particular purpose, or will operate in" at 6329.01,-830.67 h45
  text ".Layer_Name" at 577,-858.49 h60
  text "ALTIUM DESIGNER VERSION:" at 12848.5,-923.5 h45
  text "an implementation. TI and/or its licensors do not warrant that the design is production worthy. You should" at 6329.01,-943.33 h45
  text "completely validate and test your design implementation to confirm the system functionality for your application." at 6374,-1056 h45
  text ".print_Scale" at 11393.5,-1056.83 h70
  text ".Application_BuildNumber" at 12899,-1056.83 h70
  text "1" at 739.84,-1263.5 h70
  text "2" at 3235.5,-1263.5 h70
  text "3" at 5724.84,-1263.5 h70
  text "4" at 8231.51,-1263.5 h70
  text "5" at 10730.5,-1263.5 h70
  text "6" at 13235.5,-1263.5 h70
M10 Fab Notes:
  drawing of 377 lines, arcs and shapes, not listed
  text "Layer" at 9839.12,7746.73 h60
  text "Name" at 10249.03,7746.73 h60
  text "Material" at 11108.8,7746.73 h60
  text "Thickness" at 11968.56,7746.73 h60
  text "Constant" at 12618.4,7746.73 h60
  text "Board Layer Stack" at 13188.26,7746.73 h60
  text "1" at 9839.12,7626.73 h60
  text "Top Overlay" at 10249.03,7626.73 h60
  text "2" at 9839.12,7506.73 h60
  text "Top Solder" at 10249.03,7506.73 h60
  text "Solder Resist" at 11108.8,7506.73 h60
  text "0.40mil" at 11968.56,7506.73 h60
  text "3.5" at 12618.4,7506.73 h60
  text "3" at 9839.12,7386.73 h60
  text "Top Layer" at 10249.03,7386.73 h60
  text "Copper" at 11108.8,7386.73 h60
  text "1.40mil" at 11968.56,7386.73 h60
  text "4" at 9839.12,7266.73 h60
  text "Dielectric1" at 10249.03,7266.73 h60
  text "FR-4" at 11108.8,7266.73 h60
  text "59.20mil" at 11968.56,7266.73 h60
  text "4.8" at 12618.4,7266.73 h60
  text "5" at 9839.12,7146.73 h60
  text "Bottom Layer" at 10249.03,7146.73 h60
  text "Copper" at 11108.8,7146.73 h60
  text "1.40mil" at 11968.56,7146.73 h60
  text "6" at 9839.12,7026.73 h60
  text "Bottom Solder" at 10249.03,7026.73 h60
  text "Solder Resist" at 11108.8,7026.73 h60
  text "0.40mil" at 11968.56,7026.73 h60
  text "3.5" at 12618.4,7026.73 h60
  text "DESIGN INFORMATION" at 12381.02,6810 h60
  text "(REFER ALSO ARRAY/PANEL PROFILING INFORMATION)" at 12019.46,6648.29 h60
  text "BOARD SIZE" at 11333.46,6644 h60
  text "2500MIL" at 11795.78,6516.18 h60
  text "X" at 12301.46,6516.18 h60
  text "2300MIL" at 12532.78,6516.18 h60
  text "Number of Layers :" at 11736.46,6319 h60
  text "2" at 12831.27,6309 h60
  text "MIN. TRACK WIDTH:" at 11736.46,6180 h60
  text "10" at 12832.7,6180 h60
  text "MIL" at 12987.46,6180 h60
  text "MIN. CLEARANCE:" at 11736.46,6048 h60
  text "8" at 12832.7,6048 h60
  text "MIL" at 12987.46,6048 h60
  text "MIN. VIA PAD SIZE:" at 11736.46,5916 h60
  text "24" at 12802.71,5916 h60
  text "MIL" at 12987.46,5916 h60
  text "0.05mm (2MIL)" at 12431.46,5774.29 h60
  text "MINIMUM ANNULAR RING" at 11407.23,5770 h60
  text "EXTERNAL" at 13139.46,5770 h60
  text "PER" at 11607.23,5652 h60
  text "IPC-D-275 CLASS 2 LEVEL C" at 11827.23,5652 h60
  text "MIL, HOLES" at 13315.46,5539.71 h60
  text "+/-" at 12923,5539 h60
  text "+/-" at 13777,5539 h60
  text "REGISTRATION TOLERANCES:" at 11407.23,5534 h60
  text "METAL" at 12607,5534 h60
  text "5" at 13183.2,5534 h60
  text "3" at 14016.2,5534 h60
  text "MIL" at 14132.46,5534 h60
  text "MATERIAL:" at 11332.46,5324.54 h60
  text "FR-4 High Tg" at 12318.9,5184.21 h60
  text "FR-408" at 11753.46,5175.64 h60
  text "X" at 12165.46,5175.64 h60
  text "OTHER" at 13241.46,5175.64 h60
  text "62 MIL (1.6mm) +/-10%" at 12073.56,5012.92 h60
  text "THICKNESS:" at 11407.23,5008.64 h60
  text "X" at 11945.4,5008.64 h60
  text "OTHER" at 13358.46,5008.64 h60
  text "TOLERANCE:" at 11407.23,4850.64 h60
  text "X" at 12246.53,4850.64 h60
  text "ANSI IPC-6012 TYPE 3 CLASS 2" at 12433.48,4850.64 h60
  text "OTHER +/-" at 12433.46,4694.64 h60
  text "BOW & TWIST:" at 11407.23,4537.64 h60
  text "X" at 12246.53,4537.64 h60
  text "ANSI IPC-6012 TYPE 3 CLASS 2" at 12433.48,4537.64 h60
  text "OTHER +/-" at 12433.46,4379.13 h60
  text "COPPER THICKNESS (FINISHED):" at 11332.46,4243.64 h60
  text "1.4MIL (1oz)" at 12212.46,4090.92 h60
  text "2MIL (1.4oz)" at 12979.46,4090.92 h60
  text "2.8MIL (2oz)" at 13706.46,4090.92 h60
  text "OUTER:" at 11689.46,4086.64 h60
  text "X" at 12084,4086 h60
  text "1.4MIL (1oz)" at 12212.46,3933.92 h60
  text "2.8MIL (2oz)" at 12979.46,3933.92 h60
  text "N/A" at 13706,3934.29 h60
  text "INNER SIGNAL:" at 11400.38,3929.64 h60
  text "X" at 12085.42,3929.64 h60
  text "DRILLING:" at 11332.46,3790.64 h60
  text "REFERENCE:" at 11407.23,3673.64 h60
  text "X" at 12055.46,3673.64 h60
  text "AS SHOWN" at 12242.46,3673.64 h60
  text "X" at 12956.46,3673.64 h60
  text "NC_DRILL FILES" at 13093.46,3673.64 h60
  text "PTH MIN COPPER THICKNESS:" at 11407.23,3515.64 h60
  text "X" at 12757.46,3515.64 h60
  text "1MIL" at 12894.46,3515.64 h60
  text "OTHER" at 13391.46,3515.64 h60
  text "BOARD FINISH:" at 11332.46,3356.64 h60
  text "SILKSCREEN:" at 11487.68,3238.64 h60
  text "X" at 12436.46,3238.64 h60
  text "TOP" at 12562.46,3238.64 h60
  text "BOTTOM" at 13073.46,3238.64 h60
  text "SILKSCREEN COLOR:" at 11487.68,3071.64 h60
  text "X" at 12435.42,3071.64 h60
  text "WHITE" at 12562.46,3071.64 h60
  text "OTHER" at 13073.46,3071.64 h60
  text "SOLDER RESIST COLOR:" at 11487.68,2901.64 h60
  text "X" at 12055.42,2742.44 h60
  text "GREEN" at 12182.46,2742.44 h60
  text "BLUE" at 12773.46,2742.44 h60
  text "OTHER" at 13311.46,2742.44 h60
  text "IMMERSION GOLD (ENIG)" at 12393.46,2553.92 h60
  text "ENEPIG" at 13731,2550.64 h60
  text "SURFACE FINISH:" at 11332.46,2549.64 h60
  text "X" at 12206.51,2549.64 h60
  text "IMM. TIN/SILVER OR EQUIV" at 11662,2392.64 h60
  text "OTHER" at 13093.46,2392.64 h60
  text "ARRAY/PANEL:" at 11332.46,2213.64 h60
  text "CUT AND TRIM PER MECH LAYER 1" at 12393.46,2209.35 h60
  text "N.C. ROUTE" at 12393.46,2057.64 h60
  text "X" at 13072.46,2057.64 h60
  text "V. SCORE" at 13259.46,2057.64 h60
  text "CERTIFICATION:" at 11332.46,1920.64 h60
  text "MATERIALS AND WORKMANSHIP FOR ALL PCBS" at 12057.46,1920.64 h60
  text "TO MEET OR EXCEED THE REQUIREMENTS OF:" at 12057.46,1822.64 h60
  text "X" at 11683.96,1686.13 h60
  text "ANSI IPC-A-600F CLASS ->" at 11822.96,1686.13 h60
  text "X" at 13462.02,1686.13 h60
  text "2" at 13580.96,1686.14 h60
  text "1" at 13265.96,1684.64 h60
  text "3" at 13934.96,1684.64 h60
  text "X" at 11686.02,1526.64 h60
  text "UL 94V-0" at 11822.96,1526.64 h60
  text "X" at 12498.02,1526.64 h60
  text "RoHS" at 12634.96,1526.64 h60
  text "OTHER" at 13279.36,1526.64 h60
  text "PER ORDER" at 13676.42,1526.64 h60
  text "ADDITIONAL REQUIREMENTS:" at 11332.46,1385.64 h60
  text "MICROSECTION:" at 11407.23,1270.64 h60
  text "YES" at 12312.96,1270.64 h60
  text "REQUIRED" at 13174.46,1114.49 h60
  text "BARE BOARD ELEC. TEST:" at 11407.23,1111.64 h60
  text "NONE" at 12712.96,1111.64 h60
  text "X" at 13047.46,1111.64 h60
  text "PER ORDER" at 13766.46,1111.64 h60
  text "MANUFACTURER'S UL:" at 11407.23,954.64 h60
  text "RAIL" at 12572.96,950.35 h60
  text "METAL" at 13064.77,950.35 h60
  text "X" at 13440,950 h60
  text "SILK" at 13576.46,950.35 h60
  text ".Layer_Name" at 577,-858.49 h60
M11 Gerber Information:
  lines w10: -292,-930.17 6308,-930.17 ; -292,-726.83 6310,-726.83 ; -292,-523.5 -292,-1133.5 3713,-1133.5 6310,-1133.5 6310,-523.5 -291.5,-523.5 -291.5,-1133.5 1284,-1133.5 ; 2173,-1133.5 2173,-523.5 ; 3440,-726.83 3440,-523.5 ; 4280,-726.83 4280,-523.5 ; 4902,-1140 4902,-937.17
  text "ALL ARTWORK VIEWED FROM TOP SIDE" at -228.5,-655.67 h60
  text "BOARD #:" at 2248,-655.67 h60
  text ".PRJ_Number" at 2793.5,-655.67 h60
  text "REV:" at 3638,-655.67 h60
  text ".PCB_Rev" at 3929.5,-655.67 h60
  text "SVN REV:" at 4476,-655.67 h60
  text ".VersionControl_RevNumber" at 4982,-655.67 h60
  text "LAYER NAME =" at -228.5,-858.49 h60
  text "PLOT NAME =" at -228.5,-1064.34 h60
  text ".plot_File_Name" at 577,-1064.34 h60
  text "GENERATED    :" at 2250,-1064.34 h60
  text ".Print_Date" at 3119.5,-1064.34 h60
  text ".Print_Time" at 3848.5,-1064.34 h60
  text "TEXAS INSTRUMENTS" at 5113,-1064.34 h60
M12 Stackup:
  text ".Layer_Name" at 577,-858.49 h60
M13 Component Bodies Top:
  text ".Layer_Name" at 577,-858.49 h60
M14 Component Bodies Bottom:
  text ".Layer_Name" at 577,-858.49 h60
M15 Courtyards Top:
  text ".Layer_Name" at 577,-858.49 h60
M16 Courtyards Bottom:
  text ".Layer_Name" at 577,-858.49 h60
Drill Drawing:
  lines w10: 2599.09,1091.42 2626.72,1105.23 2654.34,1091.42 2640.53,1119.04 2654.34,1146.67 2626.72,1132.86 2599.09,1146.67 2612.9,1119.04 2599.09,1091.42 ; 2599.09,1229.55 2612.9,1229.55 2626.72,1215.74 2640.53,1229.55 2654.34,1229.55 2640.53,1243.36 2654.34,1257.18 2640.53,1257.18 2626.72,1270.99 2612.9,1257.18 2599.09,1257.18 2612.9,1243.36 2599.09,1229.55 ; 2599.09,1395.31 2654.34,1395.31 2626.72,1340.06 2599.09,1395.31 ; 2599.09,1492 2626.72,1464.38 2654.34,1492 2626.72,1519.63 2599.09,1492 ; 2599.09,1602.51 2612.9,1602.51 2612.9,1588.7 2640.53,1588.7 2640.53,1602.51 2654.34,1602.51 2654.34,1630.14 2640.53,1630.14 2640.53,1643.95 2612.9,1643.95 2612.9,1630.14 2599.09,1630.14 2599.09,1602.51 ; 2599.09,1837.34 2599.09,1851.15 2612.9,1864.96 2599.09,1878.78 2599.09,1892.59 2612.9,1892.59 2626.72,1878.78 2640.53,1892.59 2654.34,1892.59 2654.34,1878.78 2640.53,1864.96 2654.34,1851.15 2654.34,1837.34 2640.53,1837.34 2626.72,1851.15 2612.9,1837.34 2599.09,1837.34 ; 2610.14,1102.47 2626.72,1110.76 2643.29,1102.47 2635.01,1119.04 2643.29,1135.62 2626.72,1127.33 2610.14,1135.62 2618.43,1119.04 2610.14,1102.47 ; 2610.14,1235.08 2618.43,1235.08 2626.72,1226.79 2635.01,1235.08 2643.29,1235.08 2635.01,1243.36 2643.29,1251.65 2635.01,1251.65 2626.72,1259.94 2618.43,1251.65 2610.14,1251.65 2618.43,1243.36 2610.14,1235.08 ; 2610.14,1384.26 2643.29,1384.26 2626.72,1351.11 2610.14,1384.26 ; 2610.14,1608.04 2618.43,1608.04 2618.43,1599.75 2635.01,1599.75 2635.01,1608.04 2643.29,1608.04 2643.29,1624.61 2635.01,1624.61 2635.01,1632.9 2618.43,1632.9 2618.43,1624.61 2610.14,1624.61 2610.14,1608.04 ; 2610.14,1848.39 2610.14,1856.68 2618.43,1864.96 2610.14,1873.25 2610.14,1881.54 2618.43,1881.54 2626.72,1873.25 2635.01,1881.54 2643.29,1881.54 2643.29,1873.25 2635.01,1864.96 2643.29,1856.68 2643.29,1848.39 2635.01,1848.39 2626.72,1856.68 2618.43,1848.39 2610.14,1848.39
  lines w12: 2549,1054.12 4527.02,1054.12 ; 2549,2173 4527.02,2173 ; 2886.86,929.8 2886.86,2297.32 ; 3218.86,929.8 3218.86,2297.32 ; 3855.43,929.8 3855.43,2297.32 ; 4114.57,929.8 4114.57,2297.32 ; 2549,929.8 4527.02,929.8 4527.02,2297.32 2549,2297.32 2549,929.8
  text "Symbol" at 2623.59,2210.3 h72
  text "Quantity" at 2924.16,2210.3 h72
  text "Finished Hole Size" at 3256.16,2210.3 h72
  text "Plated" at 3892.72,2210.3 h72
  text "Hole Type" at 4151.86,2210.3 h72
  text "21" at 2924.16,2085.98 h60
  text "7.87mil (0.200mm)" at 3256.16,2085.98 h60
  text "PTH" at 3892.72,2085.98 h60
  text "Round" at 4151.86,2085.98 h60
  text "C" at 2598.31,2075.99 h55.25
  text "4" at 2924.16,1961.66 h60
  text "12.00mil (0.305mm)" at 3256.16,1961.66 h60
  text "PTH" at 3892.72,1961.66 h60
  text "Round" at 4151.86,1961.66 h60
  text "A" at 2598.31,1951.67 h55.25
  text "44" at 2924.16,1837.34 h60
  text "20.00mil (0.508mm)" at 3256.16,1837.34 h60
  text "PTH" at 3892.72,1837.34 h60
  text "Round" at 4151.86,1837.34 h60
  text "6" at 2924.16,1713.02 h60
  text "28.00mil (0.711mm)" at 3256.16,1713.02 h60
  text "PTH" at 3892.72,1713.02 h60
  text "Round" at 4151.86,1713.02 h60
  text "B" at 2598.31,1703.03 h55.25
  text "1" at 2924.16,1588.7 h60
  text "35.43mil (0.900mm)" at 3256.16,1588.7 h60
  text "PTH" at 3892.72,1588.7 h60
  text "Round" at 4151.86,1588.7 h60
  text "25" at 2924.16,1464.38 h60
  text "40.00mil (1.016mm)" at 3256.16,1464.38 h60
  text "PTH" at 3892.72,1464.38 h60
  text "Round" at 4151.86,1464.38 h60
  text "5" at 2924.16,1340.06 h60
  text "49.21mil (1.250mm)" at 3256.16,1340.06 h60
  text "PTH" at 3892.72,1340.06 h60
  text "Round" at 4151.86,1340.06 h60
  text "7" at 2924.16,1215.74 h60
  text "51.18mil (1.300mm)" at 3256.16,1215.74 h60
  text "PTH" at 3892.72,1215.74 h60
  text "Round" at 4151.86,1215.74 h60
  text "2" at 2924.16,1091.42 h60
  text "62.99mil (1.600mm)" at 3256.16,1091.42 h60
  text "PTH" at 3892.72,1091.42 h60
  text "Slot" at 4151.86,1091.42 h60
  text "115 Total" at 2924.16,967.1 h60
  text "Slot definitions :" at 2623.59,880.07 h60
  text "Routed Path Length" at 3074.31,880.07 h60
  text "= Calculated from tool start centre position to tool end centre position." at 3614.05,880.07 h60
  text "Hole Length" at 3074.31,830.35 h60
  text "= Routed Path Length + Tool Size = Slot length as defined in the PCB layout" at 3414.24,830.35 h60
  text ".Layer_Name" at 577,-858.49 h60

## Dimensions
0,0 to 0,2300 on M2 Board Dimensions
0,0 to 2500,0 on M2 Board Dimensions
